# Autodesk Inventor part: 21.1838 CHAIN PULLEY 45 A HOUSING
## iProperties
Created: 2007-05
Part Number: 21.1838 CHAIN PULLEY 45 A HOUSING
Document SubType Name: Modeling
Designer: Andy Moles
Material: Aluminum-6061
Density: 2.71 g/cm^3
Mass: 142.356 g
Surface Area: 265.851 cm^2
Volume: 52.53 cm^3
Author: Andy Moles
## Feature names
1. Extrusion1
2. Extrusion2
3. Extrusion3
4. Extrusion4
5. Extrusion5
6. Mirror1
7. Chamfer1
8. Chamfer2
9. Extrusion6
10. Extrusion7
11. Mirror2
